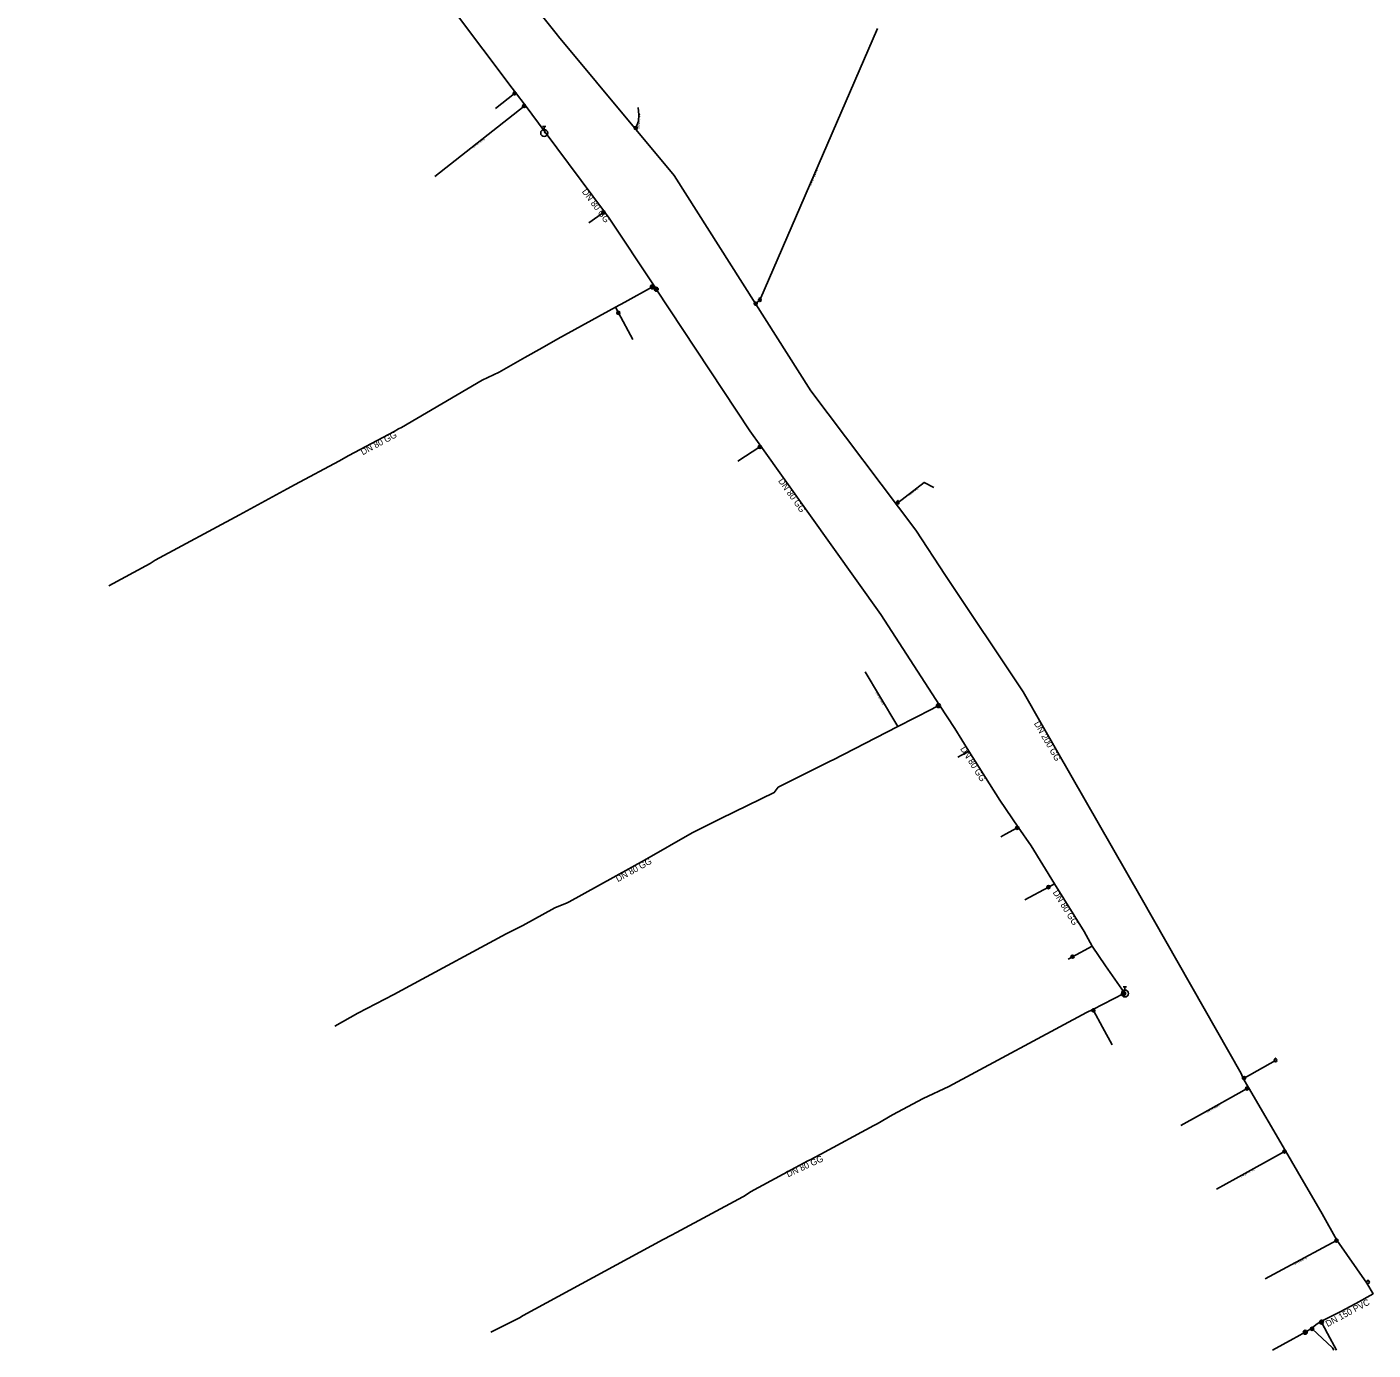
# Model space of a CAD drawing. Extents: x -482851 to -482354, y -1127969 to -1127406.
# Drawn here: x -482694.9 to -482354.3, y -1127969.2 to -1127634.2 of the extents above; entities that cross this region are included whole.
import ezdxf

# ---------------------------------------------------------------- set-up
doc = ezdxf.new("R2010")
doc.units = 0
for name, color, linetype in [('_hydrantova_odbocka_', 7, 'Continuous'), ('_pripojka_prevzato_z_dokumentace_', 7, 'Continuous'), ('_pripojka_priblizne_', 7, 'Continuous'), ('_voda_smvak_prevzato_z_dokumentace_', 7, 'Continuous'), ('Default', 7, 'Continuous'), ('MoLevel 27', 7, 'Continuous'), ('MoLevel 28', 7, 'Continuous'), ('MoLevel 30', 7, 'Continuous'), ('MoLevel 32', 7, 'Continuous'), ('MoLevel 46', 7, 'Continuous'), ('MoLevel 53', 7, 'Continuous'), ('MoLevel 55', 7, 'Continuous')]:
    doc.layers.add(name, color=color, linetype=linetype)

# ---------------------------------------------------------------- blocks, each defined once
blk = doc.blocks.new('_uzaver_')
at = {"layer": 'Default'}
for p, q in [((-0.000035, -0.000035), (0.000035, 0.000035)), ((0.000035, -0.000035), (-0.000035, 0.000035))]:
    blk.add_line(p, q, dxfattribs=at)
for radius in [0.00005, 0.0000025]:
    blk.add_circle((0, 0), radius, dxfattribs=at)
blk = doc.blocks.new('_uzaver_pripojka_')
at = {"layer": 'Default'}
for p, q in [((-0.000035, -0.000035), (0.000035, 0.000035)), ((0.000035, -0.000035), (-0.000035, 0.000035))]:
    blk.add_line(p, q, dxfattribs=at)
for radius in [0.00005, 0.0000025]:
    blk.add_circle((0, 0), radius, dxfattribs=at)
blk = doc.blocks.new('_hydrant_voda_')
at = {"layer": 'Default'}
for p, q in [((-0.000023, 0.000095), (0.000023, 0.000095)), ((0, 0.000095), (0, 0.00005))]:
    blk.add_line(p, q, dxfattribs=at)
blk.add_circle((0, 0), 0.00005, dxfattribs=at)
blk = doc.blocks.new('_sachta_voda_')
at = {"layer": 'Default'}
blk.add_lwpolyline([(-0.00001, 0.000065), (0, 0.000035), (0.00001, 0.000065)], dxfattribs=at)
blk.add_circle((0, 0), 0.000035, dxfattribs=at)

msp = doc.modelspace()

# ---------------------------------------------------------------- linework, layer by layer
at = {"layer": '_hydrantova_odbocka_'}
for p, q in [((-482564.03, -1127661.08), (-482563.8, -1127660.9)), ((-482417.23, -1127878.73), (-482417.07, -1127878.95))]:
    msp.add_line(p, q, dxfattribs=at)
at = {"layer": '_pripojka_prevzato_z_dokumentace_'}
for p, q in [((-482571.51, -1127651.06), (-482571.27, -1127650.87)), ((-482569.12, -1127654.27), (-482568.88, -1127654.08)), ((-482549.02, -1127681.2), (-482548.78, -1127681.03)), ((-482545.25, -1127706.62), (-482546.02, -1127705.18)), ((-482509.45, -1127740.56), (-482509.2, -1127740.39)), ((-482482.83, -1127797.54), (-482479.2, -1127803.6)), ((-482479.2, -1127803.6), (-482474.55, -1127811.36)), ((-482459.35, -1127819.09), (-482456.55, -1127817.59)), ((-482434.87, -1127851.16), (-482436.42, -1127852.01)), ((-482430.33, -1127869.63), (-482425.38, -1127866.94)), ((-482425.04, -1127883.22), (-482425.19, -1127882.96)), ((-482387.1, -1127900.45), (-482386.92, -1127900.35)), ((-482386.15, -1127902.99), (-482385.75, -1127902.76)), ((-482376.67, -1127918.95), (-482376.4, -1127918.81)), ((-482363.51, -1127941.5), (-482363.4, -1127941.42))]:
    msp.add_line(p, q, dxfattribs=at)
msp.add_lwpolyline([(-482447.32, -1127838.64), (-482444.31, -1127837), (-482444.04, -1127836.86)], dxfattribs=at)
at = {"layer": '_pripojka_priblizne_'}
for p, q in [((-482509.48, -1127703.42), (-482479.71, -1127634.6)), ((-482576.37, -1127654.89), (-482571.51, -1127651.06)), ((-482591.74, -1127672.09), (-482569.12, -1127654.27)), ((-482552.74, -1127683.8), (-482549.02, -1127681.2)), ((-482510.52, -1127704.28), (-482509.48, -1127703.42)), ((-482541.64, -1127713.35), (-482545.25, -1127706.62)), ((-482515.05, -1127744.21), (-482509.45, -1127740.56)), ((-482474.99, -1127755), (-482474.55, -1127754.68)), ((-482448.45, -1127839.26), (-482447.32, -1127838.64)), ((-482436.42, -1127852.01), (-482442.36, -1127855.23)), ((-482431.44, -1127870.23), (-482430.33, -1127869.63)), ((-482422.72, -1127887.49), (-482425.04, -1127883.22)), ((-482420.3, -1127891.94), (-482422.72, -1127887.49)), ((-482386.92, -1127900.35), (-482378.96, -1127895.88)), ((-482398.18, -1127909.74), (-482386.15, -1127902.99)), ((-482402.88, -1127912.39), (-482398.18, -1127909.74)), ((-482388.96, -1127925.78), (-482376.67, -1127918.95)), ((-482393.85, -1127928.49), (-482388.96, -1127925.78)), ((-482376.1, -1127948.27), (-482363.51, -1127941.5)), ((-482381.58, -1127951.22), (-482376.1, -1127948.27))]:
    msp.add_line(p, q, dxfattribs=at)
for points in [[(-482540.93, -1127660.03), (-482540.83, -1127659.83), (-482540.18, -1127658.12), (-482540.06, -1127656.46), (-482540.24, -1127654.67)], [(-482474.55, -1127754.68), (-482467.83, -1127749.54), (-482465.42, -1127750.84)], [(-482369.88, -1127963.69), (-482369.69, -1127963.86), (-482364.51, -1127968.66), (-482364.18, -1127969.23)]]:
    msp.add_lwpolyline(points, dxfattribs=at)
at = {"layer": '_voda_smvak_prevzato_z_dokumentace_'}
for p, q in [((-482572.04, -1127621.97), (-482560.66, -1127636.35)), ((-482536.23, -1127699.81), (-482536.65, -1127700.04)), ((-482536.23, -1127699.81), (-482535.68, -1127700.64)), ((-482463.98, -1127805.93), (-482464.25, -1127806.07)), ((-482417.23, -1127878.73), (-482417.37, -1127878.95)), ((-482367.41, -1127961.97), (-482367.31, -1127962.15)), ((-482374.47, -1127966.37), (-482379.75, -1127969.23)), ((-482370.29, -1127964), (-482371.42, -1127964.73))]:
    msp.add_line(p, q, dxfattribs=at)
for points in [[(-482694.95, -1127603.6), (-482694.23, -1127599.18), (-482691.97, -1127583.92), (-482689.56, -1127567.61), (-482679.18, -1127553.95), (-482676.4, -1127550.29), (-482673.12, -1127552.99), (-482664.93, -1127559.73), (-482657.29, -1127565.93), (-482656.66, -1127566.46), (-482626.44, -1127591.74), (-482622.92, -1127594.63), (-482595.91, -1127616.84), (-482593.02, -1127620.91), (-482592.52, -1127621.61), (-482587.02, -1127630.02), (-482572.11, -1127649.75), (-482571.27, -1127650.87), (-482568.88, -1127654.08), (-482563.8, -1127660.9)], [(-482560.66, -1127636.35), (-482560.42, -1127636.64), (-482531.11, -1127671.83), (-482496.51, -1127726.36), (-482469.97, -1127761.68), (-482462.44, -1127773.14), (-482442.77, -1127802.59), (-482438.04, -1127811.03), (-482412.92, -1127854.72), (-482387.62, -1127899.23), (-482387.1, -1127900.45), (-482385.75, -1127902.76), (-482376.4, -1127918.81), (-482373.38, -1127923.99), (-482367.15, -1127934.75), (-482363.4, -1127941.42), (-482355.84, -1127952.29)], [(-482563.8, -1127660.9), (-482548.78, -1127681.03), (-482547.56, -1127682.66), (-482536.23, -1127699.81)], [(-482536.65, -1127700.04), (-482543.65, -1127703.88), (-482546.02, -1127705.18), (-482560.6, -1127713.18), (-482564.57, -1127715.44), (-482568.97, -1127717.95), (-482575.39, -1127721.6), (-482579.77, -1127723.67), (-482600.17, -1127735.62), (-482600.87, -1127736.01), (-482602.01, -1127736.63), (-482613.46, -1127742.76), (-482616.02, -1127744.13), (-482627.07, -1127750.06), (-482629.12, -1127751.16), (-482641.17, -1127757.74), (-482662.47, -1127769.24), (-482663.76, -1127770.09), (-482674.24, -1127775.7)], [(-482535.68, -1127700.64), (-482512.01, -1127736.46), (-482509.2, -1127740.39), (-482478.8, -1127783), (-482463.98, -1127805.93)], [(-482464.25, -1127806.07), (-482465.93, -1127806.93), (-482474.55, -1127811.36), (-482491.07, -1127819.86), (-482491.29, -1127819.96), (-482504.79, -1127826.67), (-482505.34, -1127827.39), (-482505.81, -1127828.02), (-482519.29, -1127834.66), (-482526.61, -1127838.3), (-482538.66, -1127845.2), (-482557.69, -1127855.71), (-482558.2, -1127855.98), (-482561.31, -1127857.27), (-482569.42, -1127861.76), (-482573.62, -1127863.87), (-482598.01, -1127877.01), (-482602.07, -1127879.2), (-482611.16, -1127883.96), (-482616.98, -1127887.18)], [(-482463.98, -1127805.93), (-482460.14, -1127811.89), (-482456.55, -1127817.59), (-482448.74, -1127830.01), (-482444.04, -1127836.86)], [(-482444.04, -1127836.86), (-482440.81, -1127841.58), (-482434.87, -1127851.16), (-482427.39, -1127863.25), (-482425.38, -1127866.94), (-482421.97, -1127871.93), (-482417.23, -1127878.73)], [(-482417.37, -1127878.95), (-482425.19, -1127882.96), (-482426.75, -1127883.79), (-482461.62, -1127902.5), (-482468.14, -1127905.53), (-482475.85, -1127909.69), (-482479.72, -1127911.92), (-482480.61, -1127912.4), (-482494.02, -1127919.65), (-482496.75, -1127921.07), (-482497.32, -1127921.34), (-482511.78, -1127929.16), (-482513.38, -1127930.23), (-482513.78, -1127930.45), (-482530.57, -1127939.5), (-482531.81, -1127940.15), (-482533.9, -1127941.26), (-482569.36, -1127960.47), (-482570.32, -1127961.06), (-482577.5, -1127964.68)], [(-482355.84, -1127952.29), (-482354.25, -1127954.97), (-482358.65, -1127957.4), (-482362.58, -1127959.52), (-482366.43, -1127961.48), (-482367.41, -1127961.97)], [(-482367.41, -1127961.97), (-482368.43, -1127962.59), (-482370.29, -1127964)], [(-482367.31, -1127962.15), (-482365.82, -1127965.03), (-482363.54, -1127969.23)], [(-482371.42, -1127964.73), (-482373.59, -1127965.9), (-482374.47, -1127966.37)]]:
    msp.add_lwpolyline(points, dxfattribs=at)

# ---------------------------------------------------------------- block references
at = {"layer": 'MoLevel 27'}
for p, xscale, yscale, rotation in [((-482536.65, -1127700.04), 10000, 10000, -151.25178887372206), ((-482535.68, -1127700.64), 9999.999999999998, 10000, 124.628702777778), ((-482464.25, -1127806.07), 10000, 10000, -152.81316666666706), ((-482417.37, -1127878.95), 10000, 10000, 27.995474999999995), ((-482367.31, -1127962.15), 10000, 9999.999999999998, -59.44206111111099), ((-482371.42, -1127964.73), 10000, 9999.999999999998, 28.117651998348)]:
    msp.add_blockref('_uzaver_', p, dxfattribs=dict(at, xscale=xscale, yscale=yscale, rotation=rotation))
at = {"layer": 'MoLevel 28', "xscale": 17636.68430335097, "yscale": 17636.68430335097}
for p in [(-482564.03, -1127661.08), (-482417.07, -1127878.95)]:
    msp.add_blockref('_hydrant_voda_', p, dxfattribs=at)
at = {"layer": 'MoLevel 30', "xscale": 10000, "yscale": 10000}
for p in [(-482509.48, -1127703.42), (-482474.55, -1127754.68), (-482378.96, -1127895.88), (-482355.55, -1127952.06)]:
    msp.add_blockref('_sachta_voda_', p, dxfattribs=at)
at = {"layer": 'MoLevel 53'}
for p, xscale, yscale, rotation in [((-482571.51, -1127651.06), 7999.999999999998, 7999.999999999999, -141.7659583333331), ((-482569.12, -1127654.27), 8000, 8000, -141.76937500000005), ((-482549.02, -1127681.2), 7999.999999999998, 7999.999999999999, -145.01189166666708), ((-482509.45, -1127740.56), 7999.999999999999, 7999.999999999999, -146.876619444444), ((-482436.42, -1127852.01), 7999.999999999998, 7999.999999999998, -151.50113888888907), ((-482386.15, -1127902.99), 7999.999999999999, 7999.999999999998, -150.685266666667), ((-482376.67, -1127918.95), 8000, 7999.999999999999, -150.959986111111)]:
    msp.add_blockref('_uzaver_pripojka_', p, dxfattribs=dict(at, xscale=xscale, yscale=yscale, rotation=rotation))
at = {"layer": 'MoLevel 53', "xscale": 7999.999999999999, "yscale": 7999.999999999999}
for p in [(-482540.83, -1127659.83), (-482510.52, -1127704.28), (-482545.25, -1127706.62), (-482444.31, -1127837), (-482430.33, -1127869.63), (-482425.04, -1127883.22), (-482386.92, -1127900.35), (-482363.51, -1127941.5), (-482369.69, -1127963.86)]:
    msp.add_blockref('_uzaver_pripojka_', p, dxfattribs=at)

# ---------------------------------------------------------------- texts
at = {"layer": 'MoLevel 32'}
for s, rotation, p in [("DN 50 - 2'' PE", 85.9144, (-482539.87, -1127660.1)), ('DN neznámý', 38.2304, (-482581.85, -1127664.88)), ('DN 40 - 6/4 IPE', 66.6058, (-482496.45, -1127674.45)), ('DN 80 PE', 37.4358, (-482471.56, -1127752.97)), ('DN neznámý', 29.3153, (-482396.18, -1127909.14)), ("DN 25 - 1'' PE", 29.0404, (-482387.6, -1127925.54)), ('DN neznámý', 28.254, (-482374.24, -1127947.78))]:
    msp.add_text(s, height=0.455, rotation=rotation, dxfattribs=at).set_placement(p)
at = {"layer": 'MoLevel 46'}
for s, rotation, p in [('DN 80 GG', 306.7225, (-482554.57, -1127675.95)), ('DN 80 GG', 28.203, (-482609.95, -1127742.7)), ('DN 80 GG', 305.5059, (-482504.89, -1127749.2)), ('DN 200 GG', 299.8931, (-482440.14, -1127810.59)), ('DN 80 GG', 302.1651, (-482458.81, -1127817.01)), ('DN 80 GG', 28.8999, (-482545.38, -1127850.77)), ('DN 80 GG', 301.7742, (-482435.39, -1127853.38)), ('DN 80 GG', 24.6848, (-482502.3, -1127925.5)), ('DN 150 PVC', 28.3225, (-482365.74, -1127963.42))]:
    msp.add_text(s, height=1.605, rotation=rotation, dxfattribs=at).set_placement(p)
at = {"layer": 'MoLevel 55'}
msp.add_text('DN neznámý', height=0.455, rotation=300.9272, dxfattribs=at).set_placement((-482480.19, -1127802.82))

doc.saveas('drawing.dxf')
